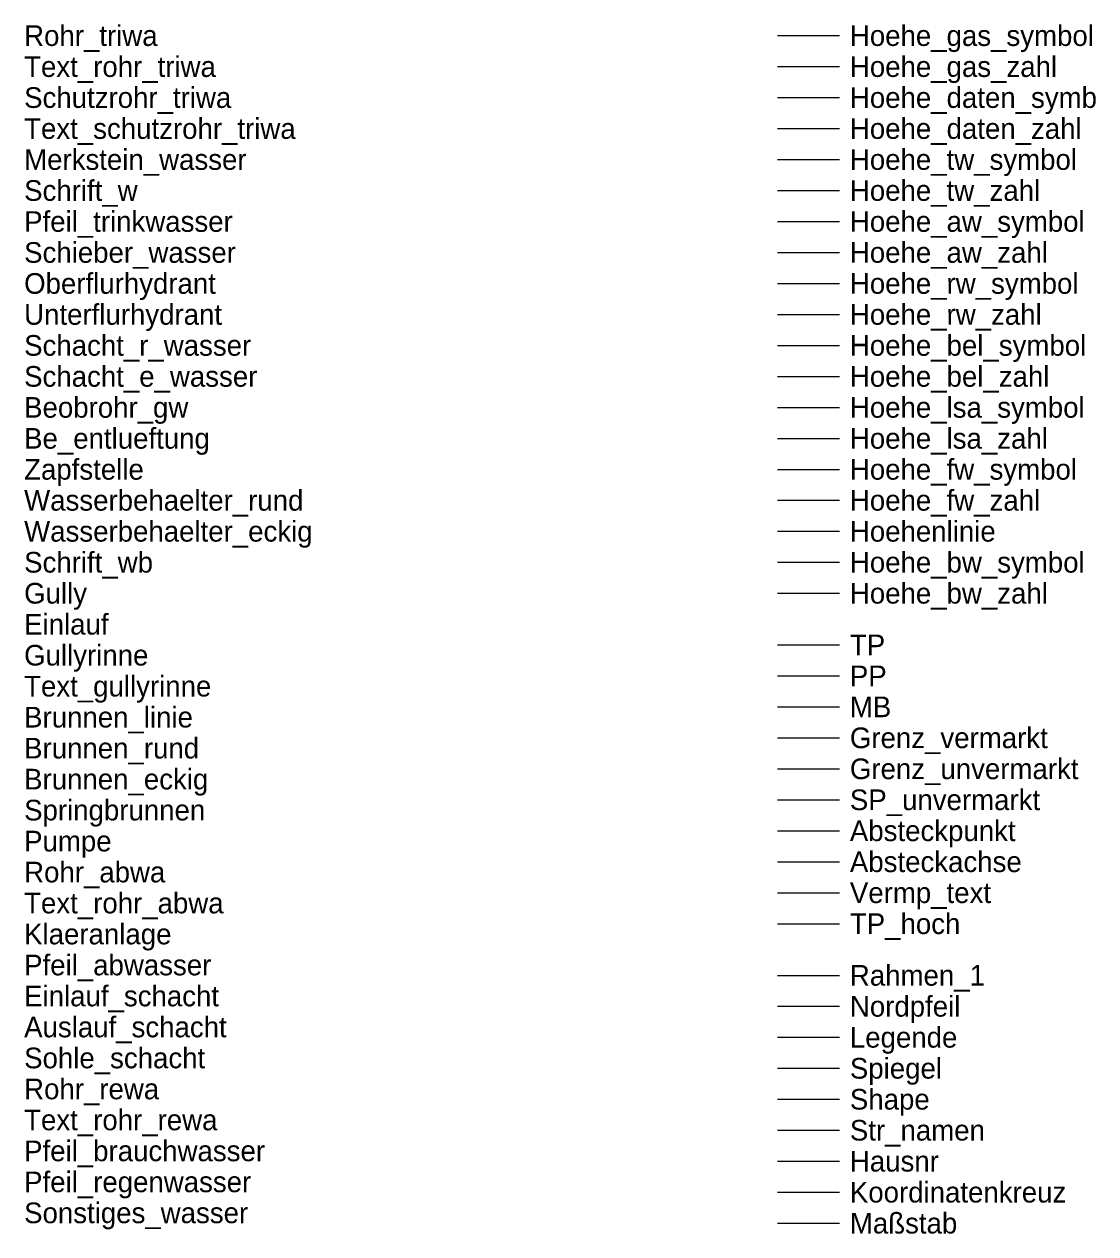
# Model space of a CAD drawing. Extents: x 0 to 177, y -135 to 1.
# Drawn here: x 123.5 to 175.4, y -58 to 0.6 of the extents above; entities that cross this region are included whole.
import ezdxf

# ---------------------------------------------------------------- set-up
doc = ezdxf.new("R2010")
doc.units = 0
for name, color, linetype in [('Absteckachse', 7, 'Continuous'), ('Absteckpunkt', 7, 'Continuous'), ('Auslauf_schacht', 7, 'Continuous'), ('Be_entlueftung', 7, 'Continuous'), ('Beobrohr_gw', 7, 'Continuous'), ('Brunnen_eckig', 7, 'Continuous'), ('Brunnen_linie', 7, 'Continuous'), ('Brunnen_rund', 7, 'Continuous'), ('Einlauf', 7, 'Continuous'), ('Einlauf_schacht', 7, 'Continuous'), ('Grenz_unvermarkt', 7, 'Continuous'), ('Grenz_vermarkt', 7, 'Continuous'), ('Gully', 7, 'Continuous'), ('Gullyrinne', 7, 'Continuous'), ('Hausnr', 7, 'Continuous'), ('Hoehe_aw_symbol', 7, 'Continuous'), ('Hoehe_aw_zahl', 7, 'Continuous'), ('Hoehe_bel_symbol', 7, 'Continuous'), ('Hoehe_bel_zahl', 7, 'Continuous'), ('Hoehe_bw_symbol', 7, 'Continuous'), ('Hoehe_bw_zahl', 7, 'Continuous'), ('Hoehe_daten_symb', 7, 'Continuous'), ('Hoehe_daten_zahl', 7, 'Continuous'), ('Hoehe_fw_symbol', 7, 'Continuous'), ('Hoehe_fw_zahl', 7, 'Continuous'), ('Hoehe_gas_symbol', 7, 'Continuous'), ('Hoehe_gas_zahl', 7, 'Continuous'), ('Hoehe_lsa_symbol', 7, 'Continuous'), ('Hoehe_lsa_zahl', 7, 'Continuous'), ('Hoehe_rw_symbol', 7, 'Continuous'), ('Hoehe_rw_zahl', 7, 'Continuous'), ('Hoehe_tw_symbol', 7, 'Continuous'), ('Hoehe_tw_zahl', 7, 'Continuous'), ('Hoehenlinie', 7, 'Continuous'), ('Klaeranlage', 7, 'Continuous'), ('Koordinatenkreuz', 7, 'Continuous'), ('Legende', 7, 'Continuous'), ('Maßstab', 7, 'Continuous'), ('MB', 7, 'Continuous'), ('Merkstein_wasser', 7, 'Continuous'), ('Nordpfeil', 7, 'Continuous'), ('Oberflurhydrant', 7, 'Continuous'), ('Pfeil_abwasser', 7, 'Continuous'), ('Pfeil_brauchwasser', 7, 'Continuous'), ('Pfeil_regenwasser', 7, 'Continuous'), ('Pfeil_trinkwasser', 7, 'Continuous'), ('PP', 7, 'Continuous'), ('Pumpe', 7, 'Continuous'), ('Rahmen_1', 7, 'Continuous'), ('Rohr_abwa', 7, 'Continuous'), ('Rohr_rewa', 7, 'Continuous'), ('Rohr_triwa', 7, 'Continuous'), ('Schacht_e_wasser', 7, 'Continuous'), ('Schacht_r_wasser', 7, 'Continuous'), ('Schieber_wasser', 7, 'Continuous'), ('Schrift_w', 7, 'Continuous'), ('Schrift_wb', 7, 'Continuous'), ('Schutzrohr_triwa', 7, 'Continuous'), ('Shape', 7, 'Continuous'), ('Sohle_schacht', 7, 'Continuous'), ('Sonstiges_wasser', 7, 'Continuous'), ('SP_unvermarkt', 7, 'Continuous'), ('Spiegel', 7, 'Continuous'), ('Springbrunnen', 7, 'Continuous'), ('Str_namen', 7, 'Continuous'), ('Text_gullyrinne', 7, 'Continuous'), ('Text_rohr_abwa', 7, 'Continuous'), ('Text_rohr_rewa', 7, 'Continuous'), ('Text_rohr_triwa', 7, 'Continuous'), ('Text_schutzrohr_triwa', 7, 'Continuous'), ('TP', 7, 'Continuous'), ('TP_hoch', 7, 'Continuous'), ('Unterflurhydrant', 7, 'Continuous'), ('Vermp_text', 7, 'Continuous'), ('Wasserbehaelter_eckig', 7, 'Continuous'), ('Wasserbehaelter_rund', 7, 'Continuous'), ('Zapfstelle', 7, 'Continuous')]:
    doc.layers.add(name, color=color, linetype=linetype)

msp = doc.modelspace()

# ---------------------------------------------------------------- linework, layer by layer
at = {"layer": 'Absteckachse'}
msp.add_line((160, -40), (163, -40), dxfattribs=at)
at = {"layer": 'Absteckpunkt'}
msp.add_line((160, -38.5), (163, -38.5), dxfattribs=at)
at = {"layer": 'Grenz_unvermarkt'}
msp.add_line((160, -35.5), (163, -35.5), dxfattribs=at)
at = {"layer": 'Grenz_vermarkt'}
msp.add_line((160, -34), (163, -34), dxfattribs=at)
at = {"layer": 'Hausnr'}
msp.add_line((160, -54.5), (163, -54.5), dxfattribs=at)
at = {"layer": 'Hoehe_aw_symbol'}
msp.add_line((160, -9), (163, -9), dxfattribs=at)
at = {"layer": 'Hoehe_aw_zahl'}
msp.add_line((160, -10.5), (163, -10.5), dxfattribs=at)
at = {"layer": 'Hoehe_bel_symbol'}
msp.add_line((160, -15), (163, -15), dxfattribs=at)
at = {"layer": 'Hoehe_bel_zahl'}
msp.add_line((160, -16.5), (163, -16.5), dxfattribs=at)
at = {"layer": 'Hoehe_bw_symbol'}
msp.add_line((160, -25.5), (163, -25.5), dxfattribs=at)
at = {"layer": 'Hoehe_bw_zahl'}
msp.add_line((160, -27), (163, -27), dxfattribs=at)
at = {"layer": 'Hoehe_daten_symb'}
msp.add_line((160, -3), (163, -3), dxfattribs=at)
at = {"layer": 'Hoehe_daten_zahl'}
msp.add_line((160, -4.5), (163, -4.5), dxfattribs=at)
at = {"layer": 'Hoehe_fw_symbol'}
msp.add_line((160, -21), (163, -21), dxfattribs=at)
at = {"layer": 'Hoehe_fw_zahl'}
msp.add_line((160, -22.5), (163, -22.5), dxfattribs=at)
at = {"layer": 'Hoehe_gas_symbol'}
msp.add_line((160, 0), (163, 0), dxfattribs=at)
at = {"layer": 'Hoehe_gas_zahl'}
msp.add_line((160, -1.5), (163, -1.5), dxfattribs=at)
at = {"layer": 'Hoehe_lsa_symbol'}
msp.add_line((160, -18), (163, -18), dxfattribs=at)
at = {"layer": 'Hoehe_lsa_zahl'}
msp.add_line((160, -19.5), (163, -19.5), dxfattribs=at)
at = {"layer": 'Hoehe_rw_symbol'}
msp.add_line((160, -12), (163, -12), dxfattribs=at)
at = {"layer": 'Hoehe_rw_zahl'}
msp.add_line((160, -13.5), (163, -13.5), dxfattribs=at)
at = {"layer": 'Hoehe_tw_symbol'}
msp.add_line((160, -6), (163, -6), dxfattribs=at)
at = {"layer": 'Hoehe_tw_zahl'}
msp.add_line((160, -7.5), (163, -7.5), dxfattribs=at)
at = {"layer": 'Hoehenlinie'}
msp.add_line((160, -24), (163, -24), dxfattribs=at)
at = {"layer": 'Koordinatenkreuz'}
msp.add_line((160, -56), (163, -56), dxfattribs=at)
at = {"layer": 'Legende'}
msp.add_line((160, -48.5), (163, -48.5), dxfattribs=at)
at = {"layer": 'Maßstab'}
msp.add_line((160, -57.5), (163, -57.5), dxfattribs=at)
at = {"layer": 'MB'}
msp.add_line((160, -32.5), (163, -32.5), dxfattribs=at)
at = {"layer": 'Nordpfeil'}
msp.add_line((160, -47), (163, -47), dxfattribs=at)
at = {"layer": 'PP'}
msp.add_line((160, -31), (163, -31), dxfattribs=at)
at = {"layer": 'Rahmen_1'}
msp.add_line((160, -45.5), (163, -45.5), dxfattribs=at)
at = {"layer": 'Shape'}
msp.add_line((160, -51.5), (163, -51.5), dxfattribs=at)
at = {"layer": 'SP_unvermarkt'}
msp.add_line((160, -37), (163, -37), dxfattribs=at)
at = {"layer": 'Spiegel'}
msp.add_line((160, -50), (163, -50), dxfattribs=at)
at = {"layer": 'Str_namen'}
msp.add_line((160, -53), (163, -53), dxfattribs=at)
at = {"layer": 'TP'}
msp.add_line((160, -29.5), (163, -29.5), dxfattribs=at)
at = {"layer": 'TP_hoch'}
msp.add_line((160, -43), (163, -43), dxfattribs=at)
at = {"layer": 'Vermp_text'}
msp.add_line((160, -41.5), (163, -41.5), dxfattribs=at)

# ---------------------------------------------------------------- texts
at = {"layer": 'Absteckachse'}
msp.add_text('Absteckachse', height=1, dxfattribs=at).set_placement((163.5, -40.5))
at = {"layer": 'Absteckpunkt'}
msp.add_text('Absteckpunkt', height=1, dxfattribs=at).set_placement((163.5, -39))
at = {"layer": 'Auslauf_schacht'}
msp.add_text('Auslauf_schacht', height=1, dxfattribs=at).set_placement((123.5, -48.5))
at = {"layer": 'Be_entlueftung'}
msp.add_text('Be_entlueftung', height=1, dxfattribs=at).set_placement((123.5, -20))
at = {"layer": 'Beobrohr_gw'}
msp.add_text('Beobrohr_gw', height=1, dxfattribs=at).set_placement((123.5, -18.5))
at = {"layer": 'Brunnen_eckig'}
msp.add_text('Brunnen_eckig', height=1, dxfattribs=at).set_placement((123.5, -36.5))
at = {"layer": 'Brunnen_linie'}
msp.add_text('Brunnen_linie', height=1, dxfattribs=at).set_placement((123.5, -33.5))
at = {"layer": 'Brunnen_rund'}
msp.add_text('Brunnen_rund', height=1, dxfattribs=at).set_placement((123.5, -35))
at = {"layer": 'Einlauf'}
msp.add_text('Einlauf', height=1, dxfattribs=at).set_placement((123.5, -29))
at = {"layer": 'Einlauf_schacht'}
msp.add_text('Einlauf_schacht', height=1, dxfattribs=at).set_placement((123.5, -47))
at = {"layer": 'Grenz_unvermarkt'}
msp.add_text('Grenz_unvermarkt', height=1, dxfattribs=at).set_placement((163.5, -36))
at = {"layer": 'Grenz_vermarkt'}
msp.add_text('Grenz_vermarkt', height=1, dxfattribs=at).set_placement((163.5, -34.5))
at = {"layer": 'Gully'}
msp.add_text('Gully', height=1, dxfattribs=at).set_placement((123.5, -27.5))
at = {"layer": 'Gullyrinne'}
msp.add_text('Gullyrinne', height=1, dxfattribs=at).set_placement((123.5, -30.5))
at = {"layer": 'Hausnr'}
msp.add_text('Hausnr', height=1, dxfattribs=at).set_placement((163.5, -55))
at = {"layer": 'Hoehe_aw_symbol'}
msp.add_text('Hoehe_aw_symbol', height=1, dxfattribs=at).set_placement((163.5, -9.5))
at = {"layer": 'Hoehe_aw_zahl'}
msp.add_text('Hoehe_aw_zahl', height=1, dxfattribs=at).set_placement((163.5, -11))
at = {"layer": 'Hoehe_bel_symbol'}
msp.add_text('Hoehe_bel_symbol', height=1, dxfattribs=at).set_placement((163.5, -15.5))
at = {"layer": 'Hoehe_bel_zahl'}
msp.add_text('Hoehe_bel_zahl', height=1, dxfattribs=at).set_placement((163.5, -17))
at = {"layer": 'Hoehe_bw_symbol'}
msp.add_text('Hoehe_bw_symbol', height=1, dxfattribs=at).set_placement((163.5, -26))
at = {"layer": 'Hoehe_bw_zahl'}
msp.add_text('Hoehe_bw_zahl', height=1, dxfattribs=at).set_placement((163.5, -27.5))
at = {"layer": 'Hoehe_daten_symb'}
msp.add_text('Hoehe_daten_symb', height=1, dxfattribs=at).set_placement((163.5, -3.5))
at = {"layer": 'Hoehe_daten_zahl'}
msp.add_text('Hoehe_daten_zahl', height=1, dxfattribs=at).set_placement((163.5, -5))
at = {"layer": 'Hoehe_fw_symbol'}
msp.add_text('Hoehe_fw_symbol', height=1, dxfattribs=at).set_placement((163.5, -21.5))
at = {"layer": 'Hoehe_fw_zahl'}
msp.add_text('Hoehe_fw_zahl', height=1, dxfattribs=at).set_placement((163.5, -23))
at = {"layer": 'Hoehe_gas_symbol'}
msp.add_text('Hoehe_gas_symbol', height=1, dxfattribs=at).set_placement((163.5, -0.5))
at = {"layer": 'Hoehe_gas_zahl'}
msp.add_text('Hoehe_gas_zahl', height=1, dxfattribs=at).set_placement((163.5, -2))
at = {"layer": 'Hoehe_lsa_symbol'}
msp.add_text('Hoehe_lsa_symbol', height=1, dxfattribs=at).set_placement((163.5, -18.5))
at = {"layer": 'Hoehe_lsa_zahl'}
msp.add_text('Hoehe_lsa_zahl', height=1, dxfattribs=at).set_placement((163.5, -20))
at = {"layer": 'Hoehe_rw_symbol'}
msp.add_text('Hoehe_rw_symbol', height=1, dxfattribs=at).set_placement((163.5, -12.5))
at = {"layer": 'Hoehe_rw_zahl'}
msp.add_text('Hoehe_rw_zahl', height=1, dxfattribs=at).set_placement((163.5, -14))
at = {"layer": 'Hoehe_tw_symbol'}
msp.add_text('Hoehe_tw_symbol', height=1, dxfattribs=at).set_placement((163.5, -6.5))
at = {"layer": 'Hoehe_tw_zahl'}
msp.add_text('Hoehe_tw_zahl', height=1, dxfattribs=at).set_placement((163.5, -8))
at = {"layer": 'Hoehenlinie'}
msp.add_text('Hoehenlinie', height=1, dxfattribs=at).set_placement((163.5, -24.5))
at = {"layer": 'Klaeranlage'}
msp.add_text('Klaeranlage', height=1, dxfattribs=at).set_placement((123.5, -44))
at = {"layer": 'Koordinatenkreuz'}
msp.add_text('Koordinatenkreuz', height=1, dxfattribs=at).set_placement((163.5, -56.5))
at = {"layer": 'Legende'}
msp.add_text('Legende', height=1, dxfattribs=at).set_placement((163.5, -49))
at = {"layer": 'Maßstab'}
msp.add_text('Maßstab', height=1, dxfattribs=at).set_placement((163.5, -58))
at = {"layer": 'MB'}
msp.add_text('MB', height=1, dxfattribs=at).set_placement((163.5, -33))
at = {"layer": 'Merkstein_wasser'}
msp.add_text('Merkstein_wasser', height=1, dxfattribs=at).set_placement((123.5, -6.5))
at = {"layer": 'Nordpfeil'}
msp.add_text('Nordpfeil', height=1, dxfattribs=at).set_placement((163.5, -47.5))
at = {"layer": 'Oberflurhydrant'}
msp.add_text('Oberflurhydrant', height=1, dxfattribs=at).set_placement((123.5, -12.5))
at = {"layer": 'Pfeil_abwasser'}
msp.add_text('Pfeil_abwasser', height=1, dxfattribs=at).set_placement((123.5, -45.5))
at = {"layer": 'Pfeil_brauchwasser'}
msp.add_text('Pfeil_brauchwasser', height=1, dxfattribs=at).set_placement((123.5, -54.5))
at = {"layer": 'Pfeil_regenwasser'}
msp.add_text('Pfeil_regenwasser', height=1, dxfattribs=at).set_placement((123.5, -56))
at = {"layer": 'Pfeil_trinkwasser'}
msp.add_text('Pfeil_trinkwasser', height=1, dxfattribs=at).set_placement((123.5, -9.5))
at = {"layer": 'PP'}
msp.add_text('PP', height=1, dxfattribs=at).set_placement((163.5, -31.5))
at = {"layer": 'Pumpe'}
msp.add_text('Pumpe', height=1, dxfattribs=at).set_placement((123.5, -39.5))
at = {"layer": 'Rahmen_1'}
msp.add_text('Rahmen_1', height=1, dxfattribs=at).set_placement((163.5, -46))
at = {"layer": 'Rohr_abwa'}
msp.add_text('Rohr_abwa', height=1, dxfattribs=at).set_placement((123.5, -41))
at = {"layer": 'Rohr_rewa'}
msp.add_text('Rohr_rewa', height=1, dxfattribs=at).set_placement((123.5, -51.5))
at = {"layer": 'Rohr_triwa'}
msp.add_text('Rohr_triwa', height=1, dxfattribs=at).set_placement((123.5, -0.5))
at = {"layer": 'Schacht_e_wasser'}
msp.add_text('Schacht_e_wasser', height=1, dxfattribs=at).set_placement((123.5, -17))
at = {"layer": 'Schacht_r_wasser'}
msp.add_text('Schacht_r_wasser', height=1, dxfattribs=at).set_placement((123.5, -15.5))
at = {"layer": 'Schieber_wasser'}
msp.add_text('Schieber_wasser', height=1, dxfattribs=at).set_placement((123.5, -11))
at = {"layer": 'Schrift_w'}
msp.add_text('Schrift_w', height=1, dxfattribs=at).set_placement((123.5, -8))
at = {"layer": 'Schrift_wb'}
msp.add_text('Schrift_wb', height=1, dxfattribs=at).set_placement((123.5, -26))
at = {"layer": 'Schutzrohr_triwa'}
msp.add_text('Schutzrohr_triwa', height=1, dxfattribs=at).set_placement((123.5, -3.5))
at = {"layer": 'Shape'}
msp.add_text('Shape', height=1, dxfattribs=at).set_placement((163.5, -52))
at = {"layer": 'Sohle_schacht'}
msp.add_text('Sohle_schacht', height=1, dxfattribs=at).set_placement((123.5, -50))
at = {"layer": 'Sonstiges_wasser'}
msp.add_text('Sonstiges_wasser', height=1, dxfattribs=at).set_placement((123.5, -57.5))
at = {"layer": 'SP_unvermarkt'}
msp.add_text('SP_unvermarkt', height=1, dxfattribs=at).set_placement((163.5, -37.5))
at = {"layer": 'Spiegel'}
msp.add_text('Spiegel', height=1, dxfattribs=at).set_placement((163.5, -50.5))
at = {"layer": 'Springbrunnen'}
msp.add_text('Springbrunnen', height=1, dxfattribs=at).set_placement((123.5, -38))
at = {"layer": 'Str_namen'}
msp.add_text('Str_namen', height=1, dxfattribs=at).set_placement((163.5, -53.5))
at = {"layer": 'Text_gullyrinne'}
msp.add_text('Text_gullyrinne', height=1, dxfattribs=at).set_placement((123.5, -32))
at = {"layer": 'Text_rohr_abwa'}
msp.add_text('Text_rohr_abwa', height=1, dxfattribs=at).set_placement((123.5, -42.5))
at = {"layer": 'Text_rohr_rewa'}
msp.add_text('Text_rohr_rewa', height=1, dxfattribs=at).set_placement((123.5, -53))
at = {"layer": 'Text_rohr_triwa'}
msp.add_text('Text_rohr_triwa', height=1, dxfattribs=at).set_placement((123.5, -2))
at = {"layer": 'Text_schutzrohr_triwa'}
msp.add_text('Text_schutzrohr_triwa', height=1, dxfattribs=at).set_placement((123.5, -5))
at = {"layer": 'TP'}
msp.add_text('TP', height=1, dxfattribs=at).set_placement((163.5, -30))
at = {"layer": 'TP_hoch'}
msp.add_text('TP_hoch', height=1, dxfattribs=at).set_placement((163.5, -43.5))
at = {"layer": 'Unterflurhydrant'}
msp.add_text('Unterflurhydrant', height=1, dxfattribs=at).set_placement((123.5, -14))
at = {"layer": 'Vermp_text'}
msp.add_text('Vermp_text', height=1, dxfattribs=at).set_placement((163.5, -42))
at = {"layer": 'Wasserbehaelter_eckig'}
msp.add_text('Wasserbehaelter_eckig', height=1, dxfattribs=at).set_placement((123.5, -24.5))
at = {"layer": 'Wasserbehaelter_rund'}
msp.add_text('Wasserbehaelter_rund', height=1, dxfattribs=at).set_placement((123.5, -23))
at = {"layer": 'Zapfstelle'}
msp.add_text('Zapfstelle', height=1, dxfattribs=at).set_placement((123.5, -21.5))

doc.saveas('drawing.dxf')
